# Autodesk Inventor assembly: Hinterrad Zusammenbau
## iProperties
Author: 42964
Shininess: 0.0
PropertySet Name: _Private Model Information
Length Units: 11269
Angle Units: 11283
Time Units: 11279
Mass Units: 11290
Length Display Precision: 3
Angle Display Precision: 2
Compacted: False
Created: 2000-11
Part Number: Hinterrad Zusammenbau
Document SubType Name: Assembly
Designer: 42964
Control State: 0
Master: False
Checked Out: False
PropertySet Name: Design Tracking Control
Density: 0.0
Volumn: 0.0
Area: 0.0
PropertySet Name: Model Information
